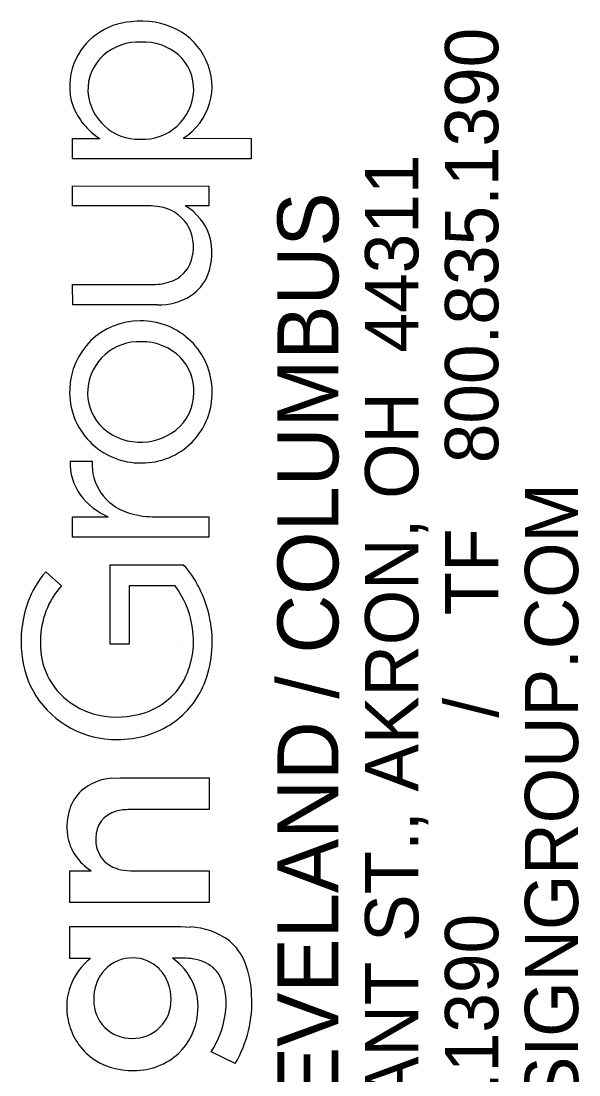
# Model space of a CAD drawing. Extents: x -0.2 to 34.2, y 0 to 22.
# Drawn here: x 32.828 to 33.35, y 3.62 to 4.607 of the extents above; entities that cross this region are included whole.
import ezdxf

# ---------------------------------------------------------------- set-up
doc = ezdxf.new("R2010")
doc.units = 0
doc.layers.add('SH_Data', color=7, linetype='Continuous')

msp = doc.modelspace()

# ---------------------------------------------------------------- linework, layer by layer
at = {"layer": 'SH_Data'}
for p, q in [((32.87646, 4.49712), (32.90203, 4.49714)), ((32.87646, 4.47814), (32.87646, 4.49712)), ((32.97985, 4.49731), (33.04352, 4.49707)), ((33.04352, 4.49707), (33.04337, 4.47814)), ((33.04337, 4.47814), (32.87646, 4.47814)), ((32.87646, 4.434), (32.87646, 4.45271)), ((32.87646, 4.45271), (33.00403, 4.45263)), ((33.00403, 4.45263), (33.00402, 4.43395)), ((32.94984, 4.43395), (32.87646, 4.434)), ((32.95773, 4.43326), (32.94984, 4.43395)), ((33.00402, 4.43395), (32.98183, 4.43395)), ((32.87648, 4.36042), (32.95399, 4.36049)), ((32.87659, 4.34142), (32.87648, 4.36042)), ((32.95567, 4.34142), (32.87659, 4.34142)), ((32.87426, 4.19506), (32.89472, 4.19506)), ((32.87646, 4.14298), (32.9097, 4.14299)), ((32.87646, 4.12399), (32.87646, 4.14298)), ((32.95099, 4.14302), (33.00403, 4.14295)), ((33.00403, 4.14295), (33.00397, 4.12399)), ((33.00397, 4.12399), (32.87646, 4.12399)), ((32.91174, 4.09784), (32.9801, 4.09791)), ((32.91174, 4.02377), (32.91174, 4.09784)), ((32.8513, 4.09148), (32.86608, 4.0784)), ((32.92942, 4.0784), (32.92926, 4.02375)), ((32.9723, 4.07827), (32.92942, 4.0784)), ((32.97494, 4.02599), (32.97494, 4.02599)), ((32.92926, 4.02375), (32.91174, 4.02377)), ((32.91278, 3.89819), (32.92128, 3.89865)), ((32.92128, 3.89865), (33.0041, 3.89865)), ((33.0041, 3.89865), (33.00411, 3.86886)), ((33.00411, 3.86886), (32.92979, 3.86879)), ((32.87381, 3.81149), (32.89391, 3.81154)), ((32.87381, 3.78168), (32.87381, 3.81149)), ((32.93062, 3.81154), (33.00409, 3.81154)), ((33.00409, 3.81154), (33.00411, 3.78178)), ((33.00411, 3.78178), (32.87381, 3.78168)), ((32.87383, 3.72935), (32.87383, 3.75922)), ((32.87383, 3.75922), (32.9773, 3.75922)), ((32.9773, 3.75922), (32.98685, 3.75884)), ((32.8933, 3.72935), (32.87383, 3.72935)), ((32.98257, 3.72955), (32.96981, 3.7296)), ((33.02854, 3.6309), (33.00614, 3.64197))]:
    msp.add_line(p, q, dxfattribs=at)
for points in [[(32.97985, 4.49731), (33.04352, 4.49707), (33.04337, 4.47814), (32.87646, 4.47814)], [(32.87646, 4.47814), (32.87646, 4.49712), (32.90203, 4.49714)], [(32.95773, 4.43326), (32.94984, 4.43395), (32.87646, 4.434), (32.87646, 4.45271), (33.00403, 4.45263), (33.00402, 4.43395), (32.98183, 4.43395)], [(32.95567, 4.34142), (32.87659, 4.34142), (32.87648, 4.36042), (32.95399, 4.36049)], [(32.87426, 4.19506), (32.89472, 4.19506)], [(32.95099, 4.14302), (33.00403, 4.14295), (33.00397, 4.12399), (32.87646, 4.12399)], [(32.87646, 4.12399), (32.87646, 4.14298), (32.9097, 4.14299)], [(32.9723, 4.07827), (32.92942, 4.0784), (32.92926, 4.02375), (32.91174, 4.02377), (32.91174, 4.09784), (32.9801, 4.09791)], [(32.8513, 4.09148), (32.86608, 4.0784)], [(32.91278, 3.89819), (32.92128, 3.89865), (33.0041, 3.89865), (33.00411, 3.86886), (32.92979, 3.86879)], [(32.87381, 3.78168), (32.87381, 3.81149), (32.89391, 3.81154)], [(32.93062, 3.81154), (33.00409, 3.81154), (33.00411, 3.78178), (32.87381, 3.78168)], [(32.8933, 3.72935), (32.87383, 3.72935), (32.87383, 3.75922), (32.9773, 3.75922), (32.98685, 3.75884)], [(32.98257, 3.72955), (32.96981, 3.7296)], [(33.02854, 3.6309), (33.00614, 3.64197)]]:
    msp.add_lwpolyline(points, dxfattribs=at)
for centre, radius, start, end in [((32.93575, 4.54424), 0.06243, 93.98662, 158.31194), ((32.93575, 4.54424), 0.06243, 93.98662, 158.31194), ((32.94051, 4.53249), 0.07459, 62.68889, 97.01346), ((32.94051, 4.53249), 0.07459, 62.68889, 97.01346), ((32.94617, 4.54513), 0.06076, 25.06574, 61.96022), ((32.94617, 4.54513), 0.06076, 25.06574, 61.96022), ((32.93873, 4.53616), 0.05134, 87.89653, 131.18123), ((32.93873, 4.53616), 0.05134, 87.89653, 131.18123), ((32.94244, 4.53622), 0.05127, 49.90886, 92.03625), ((32.94244, 4.53622), 0.05127, 49.90886, 92.03625), ((32.93414, 4.54273), 0.04338, 132.32887, 182.09489), ((32.93414, 4.54273), 0.04338, 132.32887, 182.09489), ((32.94648, 4.54332), 0.04327, 358.04871, 47.94467), ((32.94648, 4.54332), 0.04327, 358.04871, 47.94467), ((32.94944, 4.54603), 0.05743, 301.97764, 25.64176), ((32.94944, 4.54603), 0.05743, 301.97764, 25.64176), ((32.93189, 4.54615), 0.05815, 158.65601, 198.17101), ((32.93189, 4.54615), 0.05815, 158.65601, 198.17101), ((32.93846, 4.54414), 0.04776, 183.59741, 271.7045), ((32.93846, 4.54414), 0.04776, 183.59741, 271.7045), ((32.94211, 4.544), 0.04766, 267.31494, 357.4019), ((32.94211, 4.544), 0.04766, 267.31494, 357.4019), ((32.93524, 4.55032), 0.0627, 200.83985, 238.01619), ((32.93524, 4.55032), 0.0627, 200.83985, 238.01619), ((32.95205, 4.39598), 0.03772, 33.50082, 81.32954), ((32.95205, 4.39598), 0.03772, 33.50082, 81.32954), ((32.95733, 4.39084), 0.04959, 17.62209, 60.38974), ((32.95733, 4.39084), 0.04959, 17.62209, 60.38974), ((32.94908, 4.39549), 0.04048, 346.56179, 31.75389), ((32.94908, 4.39549), 0.04048, 346.56179, 31.75389), ((32.94837, 4.39014), 0.05838, 339.16197, 15.61485), ((32.94837, 4.39014), 0.05838, 339.16197, 15.61485), ((32.95865, 4.39215), 0.03042, 294.63214, 348.48625), ((32.95865, 4.39215), 0.03042, 294.63214, 348.48625), ((32.95241, 4.4068), 0.04633, 271.95199, 294.08943), ((32.95241, 4.4068), 0.04633, 271.95199, 294.08943), ((32.96393, 4.385), 0.04201, 303.10391, 338.15613), ((32.96393, 4.385), 0.04201, 303.10391, 338.15613), ((32.95704, 4.39855), 0.05715, 268.62699, 301.47779), ((32.95704, 4.39855), 0.05715, 268.62699, 301.47779), ((32.93929, 4.26084), 0.06552, 89.48213, 178.77752), ((32.93929, 4.26084), 0.06552, 89.48213, 178.77752), ((32.94076, 4.26013), 0.06623, 0.42265, 90.7613), ((32.94076, 4.26013), 0.06623, 0.42265, 90.7613), ((32.93891, 4.25843), 0.04846, 87.68827, 175.01696), ((32.93891, 4.25843), 0.04846, 87.68827, 175.01696), ((32.94153, 4.25635), 0.05052, 44.91202, 90.75914), ((32.94153, 4.25635), 0.05052, 44.91202, 90.75914), ((32.94449, 4.26051), 0.04549, 358.32279, 43.83486), ((32.94449, 4.26051), 0.04549, 358.32279, 43.83486), ((32.93977, 4.25939), 0.06606, 177.53728, 270.94524), ((32.93977, 4.25939), 0.06606, 177.53728, 270.94524), ((32.93579, 4.2591), 0.0453, 175.51467, 221.42047), ((32.93579, 4.2591), 0.0453, 175.51467, 221.42047), ((32.94165, 4.25871), 0.06536, 269.30834, 1.67905), ((32.94165, 4.25871), 0.06536, 269.30834, 1.67905), ((32.94425, 4.25973), 0.04572, 308.90382, 359.30947), ((32.94425, 4.25973), 0.04572, 308.90382, 359.30947), ((32.93892, 4.26333), 0.05046, 222.66255, 268.37331), ((32.93892, 4.26333), 0.05046, 222.66255, 268.37331), ((32.9406, 4.26458), 0.05178, 266.55312, 308.67253), ((32.9406, 4.26458), 0.05178, 266.55312, 308.67253), ((32.92372, 4.19261), 0.04952, 177.16211, 216.28024), ((32.92372, 4.19261), 0.04952, 177.16211, 216.28024), ((32.94229, 4.19237), 0.04764, 176.76988, 252.15044), ((32.94229, 4.19237), 0.04764, 176.76988, 252.15044), ((32.93469, 4.20154), 0.06366, 216.91526, 246.88619), ((32.93469, 4.20154), 0.06366, 216.91526, 246.88619), ((32.95184, 4.21774), 0.07473, 251.13884, 269.34694), ((32.95184, 4.21774), 0.07473, 251.13884, 269.34694), ((32.94992, 4.06536), 0.04438, 30.98913, 47.16099), ((32.94992, 4.06536), 0.04438, 30.98913, 47.16099), ((32.92657, 4.02786), 0.09855, 139.79476, 159.13696), ((32.92657, 4.02786), 0.09855, 139.79476, 159.13696), ((32.89585, 4.02617), 0.11106, 25.30315, 33.96179), ((32.89585, 4.02617), 0.11106, 25.30315, 33.96179), ((32.92393, 4.02679), 0.07753, 138.25804, 179.70064), ((32.92393, 4.02679), 0.07753, 138.25804, 179.70064), ((32.90382, 4.02698), 0.08556, 10.07509, 36.83189), ((32.90382, 4.02698), 0.08556, 10.07509, 36.83189), ((32.89533, 4.02586), 0.11166, 8.80339, 25.33484), ((32.89533, 4.02586), 0.11166, 8.80339, 25.33484), ((32.94364, 4.02567), 0.11536, 161.14379, 185.62812), ((32.94364, 4.02567), 0.11536, 161.14379, 185.62812), ((32.90919, 4.02656), 0.08036, 333.46689, 11.03668), ((32.90919, 4.02656), 0.08036, 333.46689, 11.03668), ((32.90058, 4.02576), 0.10649, 338.28866, 9.28548), ((32.90058, 4.02576), 0.10649, 338.28866, 9.28548), ((32.91305, 4.02331), 0.06676, 176.66577, 223.6912), ((32.91305, 4.02331), 0.06676, 176.66577, 223.6912), ((32.91829, 4.02298), 0.08987, 185.50773, 212.01294), ((32.91829, 4.02298), 0.08987, 185.50773, 212.01294), ((32.92361, 4.02146), 0.0652, 282.88151, 331.81475), ((32.92361, 4.02146), 0.0652, 282.88151, 331.81475), ((32.91539, 4.0261), 0.07039, 224.02147, 253.88), ((32.91539, 4.0261), 0.07039, 224.02147, 253.88), ((32.92329, 4.01767), 0.08241, 305.03061, 337.67573), ((32.92329, 4.01767), 0.08241, 305.03061, 337.67573), ((32.91705, 4.02347), 0.08908, 212.70222, 270.71399), ((32.91705, 4.02347), 0.08908, 212.70222, 270.71399), ((32.91812, 4.03853), 0.08309, 254.45353, 283.9512), ((32.91812, 4.03853), 0.08309, 254.45353, 283.9512), ((32.91923, 4.02578), 0.09138, 269.3273, 304.19632), ((32.91923, 4.02578), 0.09138, 269.3273, 304.19632), ((32.9171, 3.8485), 0.04988, 94.97056, 130.22484), ((32.9171, 3.8485), 0.04988, 94.97056, 130.22484), ((32.91188, 3.85684), 0.04016, 132.22383, 161.68229), ((32.91188, 3.85684), 0.04016, 132.22383, 161.68229), ((32.92711, 3.85241), 0.05602, 162.27398, 187.79173), ((32.92711, 3.85241), 0.05602, 162.27398, 187.79173), ((32.92947, 3.82278), 0.04601, 89.60515, 105.33026), ((32.92947, 3.82278), 0.04601, 89.60515, 105.33026), ((32.92322, 3.84288), 0.02498, 103.68683, 182.21395), ((32.92322, 3.84288), 0.02498, 103.68683, 182.21395), ((32.91866, 3.85223), 0.04763, 188.96462, 238.69865), ((32.91866, 3.85223), 0.04763, 188.96462, 238.69865), ((32.92574, 3.8398), 0.02757, 175.58441, 255.13816), ((32.92574, 3.8398), 0.02757, 175.58441, 255.13816), ((32.93023, 3.85368), 0.04215, 254.08913, 270.52838), ((32.93023, 3.85368), 0.04215, 254.08913, 270.52838), ((32.98401, 3.69388), 0.06503, 53.40344, 87.49062), ((32.98401, 3.69388), 0.06503, 53.40344, 87.49062), ((32.99011, 3.70638), 0.05141, 21.60748, 50.5577), ((32.99011, 3.70638), 0.05141, 21.60748, 50.5577), ((32.92786, 3.68412), 0.05692, 127.37482, 192.22468), ((32.92786, 3.68412), 0.05692, 127.37482, 192.22468), ((32.93187, 3.69526), 0.0346, 88.47302, 136.42562), ((32.93187, 3.69526), 0.0346, 88.47302, 136.42562), ((32.93308, 3.69562), 0.03424, 44.27195, 90.47623), ((32.93308, 3.69562), 0.03424, 44.27195, 90.47623), ((32.93915, 3.68428), 0.05472, 352.1125, 55.92295), ((32.93915, 3.68428), 0.05472, 352.1125, 55.92295), ((32.9816, 3.68324), 0.04633, 65.01687, 88.8011), ((32.9816, 3.68324), 0.04633, 65.01687, 88.8011), ((32.98754, 3.69755), 0.03085, 26.26808, 63.80301), ((32.98754, 3.69755), 0.03085, 26.26808, 63.80301), ((32.95563, 3.69313), 0.08835, 1.15143, 21.3627), ((32.95563, 3.69313), 0.08835, 1.15143, 21.3627), ((32.93635, 3.69201), 0.0401, 137.46739, 182.33237), ((32.93635, 3.69201), 0.0401, 137.46739, 182.33237), ((32.92862, 3.69199), 0.03996, 358.57141, 43.53765), ((32.92862, 3.69199), 0.03996, 358.57141, 43.53765), ((32.96059, 3.68753), 0.05953, 349.30734, 23.43071), ((32.96059, 3.68753), 0.05953, 349.30734, 23.43071), ((32.93312, 3.69003), 0.03546, 268.27882, 1.55016), ((32.93312, 3.69003), 0.03546, 268.27882, 1.55016), ((32.93031, 3.68843), 0.11383, 329.6388, 3.25998), ((32.93031, 3.68843), 0.11383, 329.6388, 3.25998), ((32.93139, 3.68969), 0.03511, 178.88208, 271.08374), ((32.93139, 3.68969), 0.03511, 178.88208, 271.08374), ((32.92957, 3.68295), 0.05837, 190.75182, 231.28919), ((32.92957, 3.68295), 0.05837, 190.75182, 231.28919), ((32.93482, 3.68307), 0.05887, 313.74196, 353.8554), ((32.93482, 3.68307), 0.05887, 313.74196, 353.8554), ((32.93232, 3.68933), 0.08771, 327.31495, 351.57478), ((32.93232, 3.68933), 0.08771, 327.31495, 351.57478), ((32.93126, 3.68712), 0.06269, 232.46061, 272.59022), ((32.93126, 3.68712), 0.06269, 232.46061, 272.59022), ((32.93448, 3.685), 0.06051, 269.6361, 312.70877), ((32.93448, 3.685), 0.06051, 269.6361, 312.70877)]:
    msp.add_arc(centre, radius, start, end, dxfattribs=at)

# ---------------------------------------------------------------- texts
for s, height, p in [('800.835.1390', 0.0498462, (33.2746, 4.19309)), ('450 GRANT ST., AKRON, OH  44311', 0.0498462, (33.19983, 3.36337)), ('AKRON / CLEVELAND / COLUMBUS', 0.056969, (33.12506, 3.16399)), ('ENVDESIGNGROUP.COM', 0.0498462, (33.34936, 3.36337)), ('TF', 0.049846, (33.2746, 4.05059)), ('/  ', 0.049846, (33.2746, 3.95483)), ('330.375.1390', 0.0498462, (33.2746, 3.36337))]:
    msp.add_text(s, height=height, rotation=90, dxfattribs=at).set_placement(p)

doc.saveas('drawing.dxf')
